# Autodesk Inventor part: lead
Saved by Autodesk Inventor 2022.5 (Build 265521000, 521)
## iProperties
Created: 2024-12
Part Number: lead
Material: Generic
Document SubType Name: Modeling
Designer: AdminForWorker
Density: 1 g/cm^3
Appearance: Default
Title: lead
Author: AdminForWorker
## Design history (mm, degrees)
feature "Body1"
feature "Body2"
feature "Body3"
feature "Body4"
feature "Body8"
feature "Body7"
feature "Body5"
feature "Body6"
feature "Body17"
feature "Body18"
feature "Body19"
feature "Body20"
feature "Body21"
feature "Body22"
feature "Body23"
feature "Body24"
body "Solid1"
body "Solid2"
body "Solid3"
body "Solid4"
body "Solid5"
body "Solid6"
body "Solid7"
body "Solid8"
body "Solid9"
body "Solid10"
body "Solid11"
body "Solid12"
body "Solid13"
body "Solid14"
body "Solid15"
body "Solid16"
